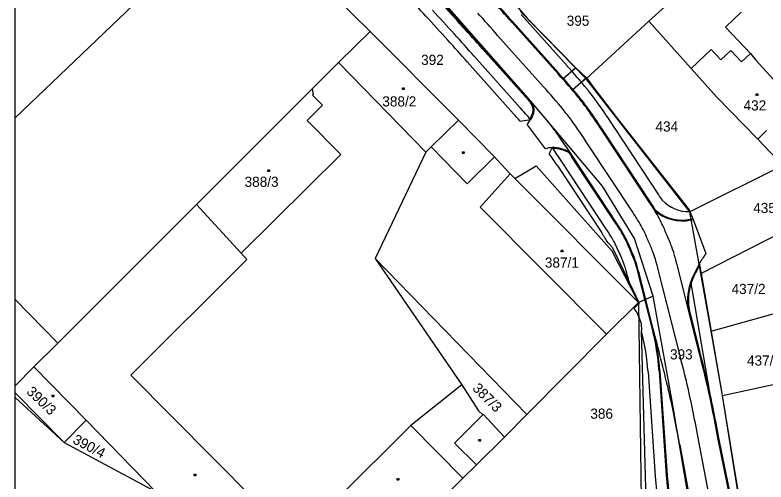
# Model space of a CAD drawing. Extents: x -639621 to -639329, y -1192893 to -1192488.
# Drawn here: x -639621.3 to -639495.6, y -1192647.6 to -1192569.5 of the extents above; entities that cross this region are included whole.
import ezdxf

# ---------------------------------------------------------------- set-up
doc = ezdxf.new("R2010")
doc.units = 0
for name, color, linetype in [('Vrstva 1', 7, 'Continuous'), ('Vrstva 19', 7, 'Continuous'), ('Vrstva 2', 7, 'Continuous'), ('Vrstva 20', 7, 'Continuous'), ('Vrstva 21', 7, 'Continuous'), ('Vrstva 22', 7, 'Continuous'), ('Vrstva 4', 7, 'Continuous'), ('Vrstva 5', 7, 'Continuous'), ('Vrstva 61', 7, 'Continuous')]:
    doc.layers.add(name, color=color, linetype=linetype)

msp = doc.modelspace()

# ---------------------------------------------------------------- linework, layer by layer
at = {"layer": 'Vrstva 1'}
for p, q in [((-639583.2, -1192550.31), (-639621.26, -1192586.7)), ((-639561.85, -1192572.23), (-639575.54, -1192558.69)), ((-639534.95, -1192583.89), (-639553.16, -1192563.18)), ((-639515.21, -1192570.53), (-639508.54, -1192564.49)), ((-639525.7, -1192580.15), (-639536.67, -1192568.89)), ((-639499.72, -1192569.01), (-639502.36, -1192571.52)), ((-639525.7, -1192580.15), (-639515.21, -1192570.53)), ((-639515.21, -1192570.53), (-639508.12, -1192578.42)), ((-639567.14, -1192577.45), (-639561.85, -1192572.23)), ((-639547.02, -1192587.1), (-639561.85, -1192572.23)), ((-639502.36, -1192571.52), (-639498.18, -1192575.92)), ((-639498.18, -1192575.92), (-639497.3, -1192577.02)), ((-639571.54, -1192581.86), (-639567.14, -1192577.45)), ((-639552.51, -1192592.45), (-639567.14, -1192577.45)), ((-639497.3, -1192577.02), (-639490.62, -1192584.36)), ((-639508.12, -1192578.42), (-639503.86, -1192583.16)), ((-639508.34, -1192602.41), (-639525.7, -1192580.15)), ((-639574.6, -1192584.92), (-639571.54, -1192581.86)), ((-639571.54, -1192581.86), (-639571.38, -1192582.77)), ((-639571.38, -1192582.77), (-639571.5, -1192582.89)), ((-639571.5, -1192582.89), (-639569.81, -1192584.58)), ((-639496.96, -1192590.28), (-639503.86, -1192583.16)), ((-639590.87, -1192601.18), (-639574.6, -1192584.92)), ((-639569.81, -1192584.58), (-639572.38, -1192587.14)), ((-639522.94, -1192598.13), (-639534.95, -1192583.89)), ((-639566.71, -1192592.83), (-639572.38, -1192587.14)), ((-639547.02, -1192587.1), (-639551.6, -1192591.57)), ((-639541.04, -1192593.2), (-639547.02, -1192587.1)), ((-639496.96, -1192590.28), (-639495.5, -1192588.82)), ((-639492.74, -1192594.64), (-639496.96, -1192590.28)), ((-639552.51, -1192592.45), (-639560.98, -1192610.22)), ((-639551.6, -1192591.57), (-639552.51, -1192592.45)), ((-639566.71, -1192592.83), (-639583.4, -1192609.34)), ((-639540.55, -1192593.7), (-639541.04, -1192593.2)), ((-639538.37, -1192596.04), (-639540.55, -1192593.7)), ((-639537.59, -1192596.82), (-639534.06, -1192594.73)), ((-639521.3, -1192608.97), (-639534.06, -1192594.73)), ((-639492.74, -1192594.64), (-639508.34, -1192602.41)), ((-639537.59, -1192596.82), (-639538.37, -1192596.04)), ((-639517.56, -1192606.86), (-639522.94, -1192598.13)), ((-639614.11, -1192624.41), (-639590.87, -1192601.18)), ((-639583.4, -1192609.34), (-639590.87, -1192601.18)), ((-639506.47, -1192612.71), (-639483.2, -1192600.88)), ((-639506.47, -1192612.71), (-639508.34, -1192602.41)), ((-639514.49, -1192616.52), (-639517.56, -1192606.86)), ((-639516.92, -1192617.59), (-639521.3, -1192608.97)), ((-639560.98, -1192610.22), (-639546.46, -1192631.38)), ((-639560.98, -1192610.22), (-639535.58, -1192636.31)), ((-639504.77, -1192622.38), (-639506.47, -1192612.71)), ((-639514.49, -1192616.52), (-639516.92, -1192617.59)), ((-639511.27, -1192634.08), (-639514.49, -1192616.52)), ((-639621.26, -1192617.1), (-639614.11, -1192624.41)), ((-639522.28, -1192622.87), (-639516.92, -1192617.59)), ((-639516.92, -1192617.59), (-639516.39, -1192654.83)), ((-639504.77, -1192622.38), (-639487.35, -1192617.54)), ((-639502.88, -1192633.13), (-639504.77, -1192622.38)), ((-639535.58, -1192636.31), (-639522.28, -1192622.87)), ((-639618.09, -1192628.37), (-639614.11, -1192624.41)), ((-639618.09, -1192628.37), (-639621.26, -1192631.52)), ((-639609.37, -1192637.29), (-639618.09, -1192628.37)), ((-639502.88, -1192633.13), (-639486.09, -1192629.51)), ((-639546.46, -1192631.38), (-639555.01, -1192638.16)), ((-639546.46, -1192631.38), (-639543.67, -1192635.71)), ((-639621.26, -1192632.68), (-639613.04, -1192640.98)), ((-639621.26, -1192633.45), (-639613.04, -1192640.98)), ((-639499.71, -1192702.08), (-639511.27, -1192634.08)), ((-639500.18, -1192649.88), (-639502.88, -1192633.13)), ((-639543.67, -1192635.71), (-639542.99, -1192636.37)), ((-639542.99, -1192636.37), (-639542.91, -1192636.29)), ((-639542.91, -1192636.29), (-639539.32, -1192640.09)), ((-639539.32, -1192640.09), (-639535.58, -1192636.31)), ((-639613.04, -1192640.98), (-639609.37, -1192637.29)), ((-639597.73, -1192649.2), (-639609.37, -1192637.29)), ((-639555.01, -1192638.16), (-639568.41, -1192651.47)), ((-639544.04, -1192644.73), (-639539.32, -1192640.09)), ((-639613.04, -1192640.98), (-639597.73, -1192649.2)), ((-639546.32, -1192646.99), (-639544.04, -1192644.73)), ((-639559.67, -1192660.27), (-639546.32, -1192646.99))]:
    msp.add_line(p, q, dxfattribs=at)
at = {"layer": 'Vrstva 19'}
for p, q in [((-639530.39, -1192579.32), (-639538.06, -1192570.73)), ((-639530.38, -1192579.33), (-639538.06, -1192570.73)), ((-639535.22, -1192583.66), (-639542.91, -1192575.06)), ((-639536.72, -1192585), (-639536.69, -1192585.03)), ((-639534.86, -1192584.07), (-639534.97, -1192584.16)), ((-639515.17, -1192600.69), (-639522.61, -1192589.42)), ((-639515.18, -1192600.68), (-639522.6, -1192589.43)), ((-639520.59, -1192604.27), (-639528.03, -1192593)), ((-639522.26, -1192605.37), (-639522.24, -1192605.41)), ((-639512.32, -1192605.93), (-639512.33, -1192605.91)), ((-639518.28, -1192608.51), (-639518.26, -1192608.56)), ((-639506.81, -1192625.7), (-639510.4, -1192611.5)), ((-639514.45, -1192621.99), (-639516.71, -1192613.08)), ((-639506.67, -1192625.66), (-639508.46, -1192618.57)), ((-639516.39, -1192622.48), (-639516.44, -1192622.32)), ((-639513.33, -1192629.04), (-639512.12, -1192646.51)), ((-639500.52, -1192655.53), (-639503.63, -1192640.24)), ((-639510.02, -1192641.42), (-639503.55, -1192676.41))]:
    msp.add_line(p, q, dxfattribs=at)
for points in [[(-639532.8, -1192581.5), (-639540.49, -1192572.89)], [(-639517.88, -1192602.48), (-639525.32, -1192591.21)], [(-639515.29, -1192607.25), (-639515.31, -1192607.2)], [(-639509.96, -1192626.5), (-639513.56, -1192612.29)], [(-639498.81, -1192682.93), (-639506.82, -1192640.84)]]:
    msp.add_lwpolyline(points, dxfattribs=at)
for centre, radius, start, end in [((-639915.1, -1192904.07), 496.75, 42.0514, 42.682), ((-640296.6, -1193247.01), 1016.24, 41.71911, 42.00177), ((-640296.99, -1193247.36), 1016.76, 41.71905, 42.00171), ((-640296.99, -1193247.36), 1013.51, 41.71905, 42.00171), ((-640296.99, -1193247.36), 1010.26, 41.71905, 42.00171), ((-639605.83, -1192647.87), 101.93, 39.3585, 42.2615), ((-639605.83, -1192647.87), 101.93, 39.3513, 42.2535), ((-639605.83, -1192647.87), 98.68, 39.3585, 42.2615), ((-639605.83, -1192647.87), 95.43, 39.3585, 42.2615), ((-639605.83, -1192647.87), 95.43, 41.9501, 42.2615), ((-639568.44, -1192616.68), 53.25, 36.281, 38.9165), ((-639568.44, -1192616.68), 53.25, 36.2973, 38.9025), ((-639568.44, -1192616.68), 50, 36.2973, 38.9025), ((-639612.67, -1192647.97), 107.42, 33.0211, 35.7729), ((-639612.67, -1192647.97), 107.42, 33.0147, 35.7649), ((-639568.44, -1192616.68), 46.75, 36.2973, 38.9025), ((-639612.67, -1192647.97), 104.17, 33.0147, 35.7649), ((-639612.67, -1192647.97), 100.92, 33.0147, 35.7649), ((-639612.67, -1192647.97), 100.92, 33.0147, 33.3619), ((-639551.08, -1192624.8), 43.25, 31.4262, 33.9124), ((-639551.08, -1192624.8), 43.25, 31.0301, 33.8941), ((-639551.08, -1192624.8), 40, 31.0476, 33.9124), ((-639534.03, -1192614.34), 23.25, 26.5507, 30.6063), ((-639554.65, -1192624.19), 46.11, 23.3606, 26.0404), ((-639551.08, -1192624.8), 36.75, 31.0476, 33.9124), ((-639534.03, -1192614.34), 20, 26.5913, 30.5725), ((-639534.03, -1192614.34), 16.75, 26.5913, 30.5725), ((-639554.65, -1192624.19), 42.86, 23.3469, 26.0207), ((-639551.77, -1192623.65), 43.25, 21.3241, 24.1881), ((-639554.65, -1192624.19), 39.61, 23.3469, 26.0207), ((-639551.77, -1192623.65), 40, 21.3416, 24.2064), ((-639551.77, -1192623.65), 36.75, 21.3416, 24.2064), ((-639533.2, -1192616.22), 23.25, 17.0196, 20.9003), ((-639533.2, -1192616.22), 16.75, 17.0534, 20.8665), ((-639533.2, -1192616.22), 20, 17.0534, 20.8665), ((-639552.42, -1192621.77), 43.25, 13.7318, 16.5958), ((-639552.42, -1192621.77), 36.75, 13.7135, 16.5783), ((-639552.42, -1192621.77), 40, 13.7135, 16.5783), ((-639499.9, -1192617.15), 8.67, 161.3225, 189.4979), ((-640053.35, -1192762.13), 556.82, 13.5036, 14.5767), ((-639553.23, -1192631.8), 40, 3.9585, 14.191), ((-639796.77, -1192699.91), 296.05, 13.3889, 14.3565), ((-639796.77, -1192699.91), 299.3, 13.388, 14.3556), ((-639796.77, -1192699.91), 299.45, 13.388, 14.3556), ((-639654.78, -1192665.7), 150, 11.4488, 13.2362), ((-639654.78, -1192665.7), 153.25, 11.4472, 13.2378), ((-639654.78, -1192665.7), 153.4, 12.4778, 13.2378), ((-639654.78, -1192665.7), 146.75, 11.4488, 13.2362), ((-639798.08, -1192693.92), 299.3, 10.3309, 11.2969), ((-639798.08, -1192693.92), 292.8, 10.3284, 11.2961), ((-639798.08, -1192693.92), 296.05, 10.3284, 11.2961), ((-639472.22, -1192643.75), 40, 183.9585, 190.494)]:
    msp.add_arc(centre, radius, start, end, dxfattribs=at)
at = {"layer": 'Vrstva 20'}
for p, q in [((-639528.88, -1192578), (-639536.57, -1192569.39)), ((-639530.26, -1192579.23), (-639537.95, -1192570.63)), ((-639535.34, -1192583.76), (-639543.02, -1192575.16)), ((-639536.72, -1192585), (-639544.4, -1192576.39)), ((-639527.39, -1192578.34), (-639529.56, -1192580.24)), ((-639525.64, -1192580.02), (-639527.99, -1192582.06)), ((-639534.8, -1192586.36), (-639535.08, -1192586.84)), ((-639513.5, -1192599.59), (-639520.94, -1192588.32)), ((-639515.04, -1192600.61), (-639522.48, -1192589.34)), ((-639528.38, -1192592.47), (-639528.49, -1192592.58)), ((-639520.72, -1192604.35), (-639528.16, -1192593.08)), ((-639529.72, -1192594.07), (-639529.7, -1192594.1)), ((-639522.26, -1192605.37), (-639529.7, -1192594.1)), ((-639508.33, -1192602.36), (-639507.76, -1192603.68)), ((-639520.13, -1192609.28), (-639520.11, -1192609.32)), ((-639520.11, -1192609.32), (-639520.09, -1192609.37)), ((-639520.09, -1192609.37), (-639520.07, -1192609.41)), ((-639518.66, -1192613.53), (-639518.65, -1192613.57)), ((-639518.49, -1192614.21), (-639518.65, -1192613.57)), ((-639514.6, -1192622.03), (-639516.85, -1192613.12)), ((-639513.48, -1192629.05), (-639512.27, -1192646.52)), ((-639515.32, -1192629.17), (-639514.12, -1192646.65)), ((-639500.25, -1192656.13), (-639503.48, -1192640.21))]:
    msp.add_line(p, q, dxfattribs=at)
msp.add_lwpolyline([(-639528.06, -1192578.92), (-639526.48, -1192580.75), (-639525.64, -1192580.02), (-639527.39, -1192578.34)], close=True, dxfattribs=at)
for points in [[(-639500.16, -1192649.44), (-639500.16, -1192649.44), (-639502.99, -1192632.47), (-639506.38, -1192612.72), (-639506.7, -1192611.03)], [(-639508.13, -1192614.37), (-639508.18, -1192614.07)], [(-639505, -1192632.56), (-639508.13, -1192614.37)], [(-639516.77, -1192620.3), (-639516.47, -1192621.08), (-639516.44, -1192622.32)]]:
    msp.add_lwpolyline(points, dxfattribs=at)
for centre, radius, start, end in [((-639915.1, -1192904.07), 496.6, 42.0514, 42.682), ((-640296.99, -1193247.36), 1016.91, 41.71905, 42.00171), ((-639915.1, -1192904.07), 494.75, 42.0514, 42.682), ((-640296.99, -1193247.36), 1010.11, 41.71905, 42.00171), ((-640296.99, -1193247.36), 1008.26, 41.71905, 42.00171), ((-639605.83, -1192647.87), 103.93, 39.3585, 42.2615), ((-639605.83, -1192647.87), 102.08, 39.3585, 42.2615), ((-639568.44, -1192616.68), 55.25, 36.2973, 38.9025), ((-639605.83, -1192647.87), 95.28, 41.9501, 42.2615), ((-639568.44, -1192616.68), 53.4, 36.2973, 38.9025), ((-639605.83, -1192647.87), 93.43, 40.6837, 42.2615), ((-639536.49, -1192585.39), 1.95, 330.1366, 38.9464), ((-639536.49, -1192585.39), 1.95, 330.1366, 38.9464), ((-639612.67, -1192647.97), 107.57, 33.0147, 35.7649), ((-639612.67, -1192647.97), 109.42, 33.0147, 35.7649), ((-639612.67, -1192647.97), 98.92, 33.0147, 34.7), ((-639531.41, -1192597.67), 5.87, 60.1819, 88.377), ((-639612.67, -1192647.97), 100.77, 33.0147, 33.3417), ((-639551.08, -1192624.8), 45.25, 32.5293, 33.9124), ((-639551.08, -1192624.8), 43.4, 31.4262, 33.9124), ((-639508.63, -1192596.56), 5.81, 222.2457, 272.9323), ((-639509.63, -1192597.01), 6.78, 229.1172, 285.6758), ((-639551.08, -1192624.8), 36.6, 31.0476, 33.9124), ((-639551.08, -1192624.8), 34.75, 31.0476, 33.9124), ((-639534.03, -1192614.34), 16.6, 26.5913, 30.5725), ((-639534.03, -1192614.34), 14.75, 26.5913, 30.5725), ((-639554.65, -1192624.19), 37.61, 23.3469, 26.0207), ((-639556.68, -1192625.13), 41.69, 23.2971, 25.9709), ((-639551.77, -1192623.65), 36.6, 21.3416, 24.2064), ((-639551.77, -1192623.65), 34.75, 21.3416, 24.2064), ((-639533.2, -1192616.22), 14.75, 17.0534, 20.8665), ((-639533.2, -1192616.22), 16.6, 17.0534, 20.8665), ((-639552.42, -1192621.77), 36.6, 13.7135, 16.5783), ((-639487.73, -1192622.12), 21.82, 150.127, 157.7543), ((-639552.42, -1192621.77), 34.75, 13.7135, 16.5783), ((-639499.9, -1192617.15), 8.67, 157.7366, 161.2497), ((-639553.23, -1192631.8), 38, 3.9585, 14.191), ((-639553.23, -1192631.8), 39.85, 3.9585, 14.191), ((-639654.78, -1192665.7), 153.4, 11.4472, 12.4778), ((-639798.08, -1192693.92), 299.45, 10.3309, 11.2969), ((-639472.22, -1192643.75), 42, 183.9585, 190.494), ((-639472.22, -1192643.75), 40.15, 183.9585, 190.494)]:
    msp.add_arc(centre, radius, start, end, dxfattribs=at)
at = {"layer": 'Vrstva 21'}
for p, q in [((-639535.55, -1192587.84), (-639534.98, -1192586.96)), ((-639534.67, -1192586.43), (-639534.98, -1192586.96)), ((-639535.55, -1192587.84), (-639532.54, -1192591.88)), ((-639507.76, -1192603.68), (-639505.65, -1192609.4)), ((-639507.76, -1192603.68), (-639505.65, -1192609.4))]:
    msp.add_line(p, q, dxfattribs=at)
for centre, radius, start, end in [((-639536.49, -1192585.39), 2.1, 330.1366, 38.9464), ((-639530.84, -1192597.52), 5.89, 94.9496, 106.83), ((-639531.41, -1192597.67), 6.02, 59.8399, 89.4179), ((-639509.63, -1192597.01), 6.93, 229.1172, 282.4035), ((-639509.63, -1192597.01), 6.93, 282.4035, 285.6758), ((-639487.73, -1192622.12), 21.97, 144.6134, 150.0119), ((-639487.73, -1192622.12), 21.97, 150.0119, 157.7543), ((-639499.9, -1192617.15), 8.82, 157.7366, 189.4979)]:
    msp.add_arc(centre, radius, start, end, dxfattribs=at)
at = {"layer": 'Vrstva 22'}
for p, q in [((-639536.73, -1192587.23), (-639534.98, -1192586.96)), ((-639531.35, -1192591.65), (-639531.86, -1192592.68))]:
    msp.add_line(p, q, dxfattribs=at)
for points in [[(-639540.67, -1192564.85), (-639540.28, -1192564.5), (-639536.66, -1192568.74), (-639535.53, -1192570), (-639527.39, -1192578.34), (-639528.06, -1192578.92)], [(-639537.82, -1192586.02), (-639545.52, -1192577.39)], [(-639526.48, -1192580.75), (-639525.64, -1192580.02), (-639524.08, -1192582.11), (-639520.35, -1192586.93), (-639508.46, -1192602.09), (-639508.33, -1192602.36)], [(-639530.55, -1192594.63), (-639523.08, -1192605.95)], [(-639522.01, -1192607.61), (-639521.35, -1192608.31), (-639518.49, -1192614.21)], [(-639518.49, -1192614.21), (-639516.79, -1192617.7), (-639517.68, -1192618.58)], [(-639517.68, -1192618.58), (-639517.21, -1192619.28), (-639516.77, -1192620.3)], [(-639513, -1192654.33), (-639515.5, -1192654.75), (-639516.43, -1192622.32)]]:
    msp.add_lwpolyline(points, dxfattribs=at)
for centre, radius, start, end in [((-640271.67, -1193233.97), 979.03, 42.72798, 43.01828), ((-639914.7, -1192903.71), 492.72, 42.0517, 42.6823), ((-640297.81, -1193248.09), 1007.86, 41.71892, 42.00158), ((-639605.83, -1192647.87), 91.93, 41.2631, 42.2794), ((-639612.67, -1192647.97), 97.92, 33.0015, 34.3782), ((-639573, -1192639.28), 60.03, 31.8459, 33.7348)]:
    msp.add_arc(centre, radius, start, end, dxfattribs=at)
at = {"layer": 'Vrstva 4'}
for p, q in [((-639508.12, -1192578.42), (-639504.77, -1192575.27)), ((-639504.77, -1192575.27), (-639503.13, -1192577.01)), ((-639503.13, -1192577.01), (-639501.44, -1192575.42)), ((-639501.44, -1192575.42), (-639499.66, -1192577.32)), ((-639499.66, -1192577.32), (-639498.18, -1192575.92)), ((-639551.6, -1192591.57), (-639545.58, -1192597.71)), ((-639541.04, -1192593.2), (-639545.58, -1192597.71)), ((-639543.41, -1192601.63), (-639538.37, -1192596.04)), ((-639516.92, -1192617.59), (-639537.59, -1192596.82)), ((-639522.28, -1192622.87), (-639543.41, -1192601.63)), ((-639582.44, -1192610.4), (-639583.4, -1192609.34)), ((-639601.86, -1192629.73), (-639582.44, -1192610.4)), ((-639574.37, -1192657.4), (-639601.86, -1192629.73)), ((-639542.99, -1192636.37), (-639547.7, -1192641.09)), ((-639546.32, -1192646.99), (-639555.01, -1192638.16)), ((-639547.7, -1192641.09), (-639544.04, -1192644.73))]:
    msp.add_line(p, q, dxfattribs=at)
at = {"layer": 'Vrstva 5'}
for points in [[(-639556.19, -1192581.66), (-639556.1, -1192581.81), (-639556.19, -1192581.96), (-639556.37, -1192581.96), (-639556.46, -1192581.81), (-639556.37, -1192581.66)], [(-639496.99, -1192582.65), (-639496.9, -1192582.8), (-639496.99, -1192582.95), (-639497.17, -1192582.95), (-639497.26, -1192582.8), (-639497.17, -1192582.65)], [(-639546.14, -1192592.37), (-639546.05, -1192592.52), (-639546.14, -1192592.67), (-639546.32, -1192592.67), (-639546.41, -1192592.52), (-639546.32, -1192592.37)], [(-639578.71, -1192595.38), (-639578.62, -1192595.53), (-639578.71, -1192595.68), (-639578.89, -1192595.68), (-639578.98, -1192595.53), (-639578.89, -1192595.38)], [(-639529.62, -1192608.81), (-639529.53, -1192608.96), (-639529.62, -1192609.11), (-639529.8, -1192609.11), (-639529.89, -1192608.96), (-639529.8, -1192608.81)], [(-639614.82, -1192633.09), (-639614.73, -1192633.24), (-639614.82, -1192633.39), (-639615, -1192633.39), (-639615.09, -1192633.24), (-639615, -1192633.09)], [(-639543.4, -1192640.51), (-639543.31, -1192640.66), (-639543.4, -1192640.81), (-639543.58, -1192640.81), (-639543.67, -1192640.66), (-639543.58, -1192640.51)], [(-639591.06, -1192646.31), (-639590.97, -1192646.46), (-639591.06, -1192646.61), (-639591.24, -1192646.61), (-639591.33, -1192646.46), (-639591.24, -1192646.31)], [(-639557.09, -1192647.03), (-639557, -1192647.18), (-639557.09, -1192647.33), (-639557.27, -1192647.33), (-639557.36, -1192647.18), (-639557.27, -1192647.03)]]:
    msp.add_lwpolyline(points, close=True, dxfattribs=at)
at = {"layer": 'Vrstva 61'}
msp.add_lwpolyline([(-639621.26, -1192893.33), (-639621.26, -1192487.83)], dxfattribs=at)

# ---------------------------------------------------------------- texts
at = {"layer": 'Vrstva 2'}
for s, p in [('395', (-639528.93, -1192571.29)), ('392', (-639553.3, -1192577.84)), ('388/2', (-639559.79, -1192584.79)), ('432', (-639499.34, -1192585.46)), ('434', (-639514.08, -1192588.99)), ('388/3', (-639582.84, -1192598.24)), ('435', (-639497.72, -1192602.62)), ('387/1', (-639532.59, -1192611.75)), ('437/2', (-639501.34, -1192616.17)), ('393', (-639511.64, -1192627.11)), ('437/4', (-639498.76, -1192628.14)), ('386', (-639524.98, -1192637.03))]:
    msp.add_text(s, height=1.7, dxfattribs=at).set_placement(p)
for s, rotation, p in [('387/3', 315.0695, (-639544.83, -1192632.07)), ('390/3', 316.5019, (-639619.47, -1192632.66)), ('390/4', 332.3155, (-639611.75, -1192641.04))]:
    msp.add_text(s, height=1.7, rotation=rotation, dxfattribs=at).set_placement(p)

doc.saveas('drawing.dxf')
